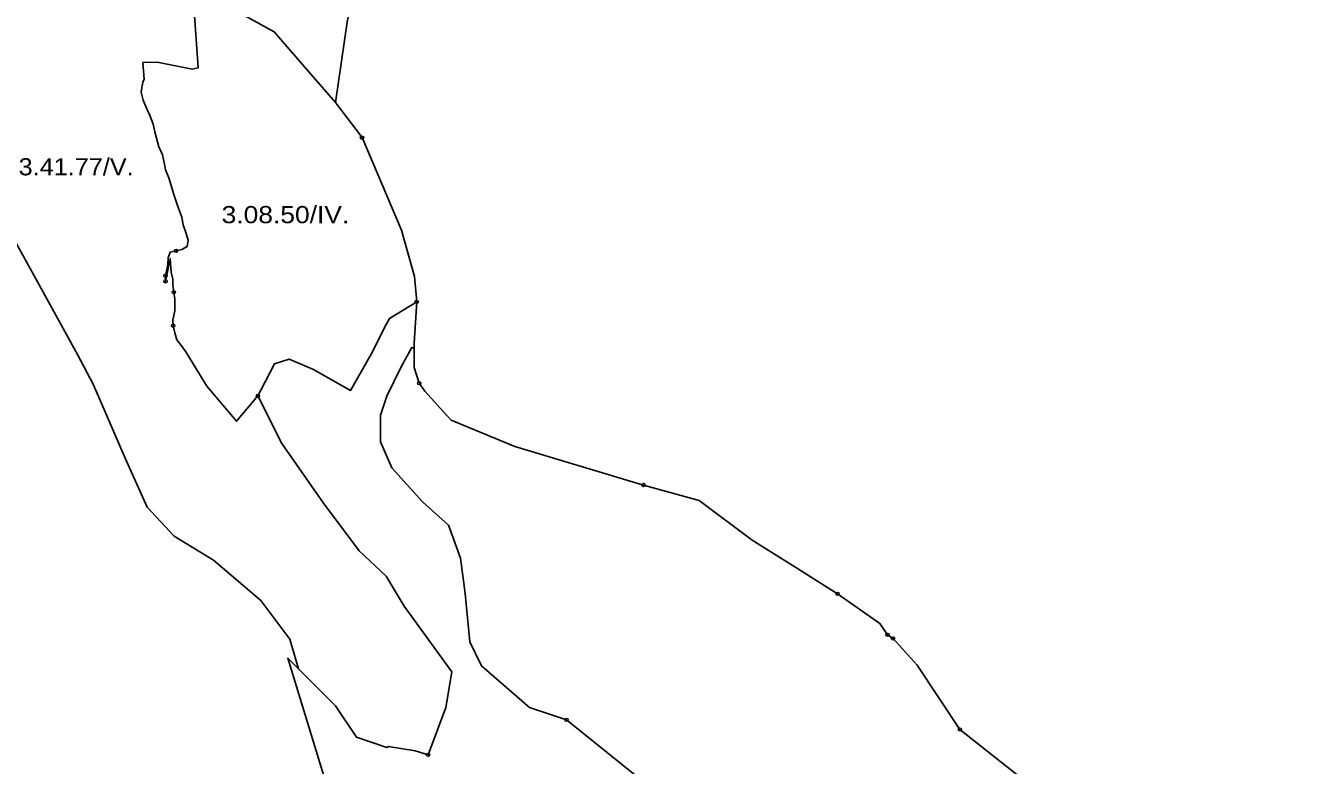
# Model space of a CAD drawing. Extents: x -650455 to -642254, y -1075222 to -1066610.
# Drawn here: x -645923 to -645184, y -1070477 to -1070045 of the extents above; entities that cross this region are included whole.
import ezdxf
from ezdxf.enums import TextEntityAlignment as Align

# ---------------------------------------------------------------- set-up
doc = ezdxf.new("R2010")
doc.units = 0
doc.header["$LTSCALE"] = 4
doc.header["$PDMODE"] = 32
doc.header["$PDSIZE"] = 2
for name, color, linetype, lineweight in [('1', 7, 'Continuous', 25), ('11', 7, 'Continuous', 13), ('12', 7, 'Continuous', 13), ('14', 7, 'Continuous', 13), ('15', 7, 'Continuous', 13)]:
    doc.layers.add(name, color=color, linetype=linetype, lineweight=lineweight)
doc.layers.add('2', color=7, linetype='Continuous')

msp = doc.modelspace()

# ---------------------------------------------------------------- linework, layer by layer
at = {"layer": '1'}
for points in [[(-645827.805, -1070170.331), (-645829.232, -1070165.834), (-645830.719, -1070161.367), (-645831.596, -1070156.856), (-645833.216, -1070152.24), (-645834.881, -1070147.654), (-645836.323, -1070143.068), (-645837.765, -1070138.483), (-645839.206, -1070133.897), (-645841.079, -1070129.341), (-645841.912, -1070124.948), (-645842.729, -1070120.556), (-645844.914, -1070115.94), (-645847.337, -1070107.036), (-645848.229, -1070102.643), (-645850.013, -1070097.968), (-645852.064, -1070093.293), (-645854.131, -1070088.618), (-645855.32, -1070084.018), (-645854.309, -1070077.93), (-645853.462, -1070076.604), (-645854.242, -1070066.719), (-645845.918, -1070066.459), (-645825.452, -1070070.498), (-645821.972, -1070069.724), (-645825.17, -1070025.403)], [(-645825.17, -1070025.403), (-645821.972, -1070069.724), (-645825.452, -1070070.498), (-645845.918, -1070066.459), (-645854.242, -1070066.719), (-645853.462, -1070076.604), (-645854.309, -1070077.93), (-645855.32, -1070084.018), (-645854.131, -1070088.618), (-645852.064, -1070093.293), (-645850.013, -1070097.968), (-645848.229, -1070102.643), (-645847.337, -1070107.036), (-645844.914, -1070115.94), (-645842.729, -1070120.556)], [(-645817.043, -1070027.048), (-645777.762, -1070048.899), (-645757.472, -1070072.051), (-645741.915, -1070090.098)], [(-645735.031, -1070041.903), (-645741.915, -1070090.098), (-645757.472, -1070072.051), (-645777.762, -1070048.899), (-645817.043, -1070027.048)], [(-645474.208, -1070360.748), (-645499.088, -1070345.198), (-645530.032, -1070322.029), (-645562.376, -1070313.01), (-645637.482, -1070290.618), (-645674.491, -1070275.223), (-645677.134, -1070272.424), (-645689.807, -1070258.381), (-645693.219, -1070253.691), (-645696.21, -1070244.446), (-645696.21, -1070233.478), (-645696.21, -1070230.279), (-645694.628, -1070206.315), (-645696, -1070191.501), (-645703.5, -1070164.501), (-645726.5, -1070110.501), (-645741.915, -1070090.098), (-645735.031, -1070041.903)], [(-645741.915, -1070090.098), (-645726.5, -1070110.501), (-645703.5, -1070164.501), (-645696, -1070191.501), (-645694.628, -1070206.315), (-645710.517, -1070216.036), (-645712.468, -1070219.418), (-645721.12, -1070236.652), (-645733.239, -1070257.86), (-645750.708, -1070248.033), (-645754.87, -1070245.692), (-645768.918, -1070239.709), (-645777.502, -1070242.31), (-645785.567, -1070257.658), (-645787.196, -1070260.996), (-645799.614, -1070275.867), (-645817.043, -1070255.317), (-645829.113, -1070235.357), (-645831.774, -1070231.886), (-645834.45, -1070228.415), (-645835.52, -1070224.275), (-645836.59, -1070220.135), (-645836.754, -1070216.783), (-645836.218, -1070214.145), (-645835.683, -1070211.506), (-645835.698, -1070204.743), (-645836.248, -1070200.618), (-645836.798, -1070196.493), (-645836.694, -1070192.948), (-645837.839, -1070188.926), (-645838.285, -1070181.137), (-645841.065, -1070194.285), (-645841.065, -1070190.985), (-645839.771, -1070184.475), (-645839.593, -1070180.632), (-645838.3, -1070177.339), (-645834.881, -1070176.492), (-645831.462, -1070175.645), (-645828.37, -1070173.935), (-645827.805, -1070170.331)], [(-645842.729, -1070120.556), (-645841.912, -1070124.948), (-645841.079, -1070129.341), (-645839.206, -1070133.897), (-645837.765, -1070138.483), (-645836.323, -1070143.068), (-645834.881, -1070147.654), (-645833.216, -1070152.24), (-645831.596, -1070156.856), (-645830.719, -1070161.367), (-645829.232, -1070165.834), (-645827.805, -1070170.331), (-645828.37, -1070173.935), (-645831.462, -1070175.645), (-645834.881, -1070176.492), (-645838.3, -1070177.339), (-645839.593, -1070180.632), (-645839.771, -1070184.475), (-645841.065, -1070190.985), (-645841.065, -1070194.285), (-645838.285, -1070181.137), (-645837.839, -1070188.926), (-645836.694, -1070192.948), (-645836.798, -1070196.493), (-645836.248, -1070200.618), (-645835.698, -1070204.743), (-645835.683, -1070211.506), (-645836.218, -1070214.145), (-645836.754, -1070216.783), (-645836.59, -1070220.135), (-645835.52, -1070224.275), (-645834.45, -1070228.415), (-645831.774, -1070231.886), (-645829.113, -1070235.357), (-645817.043, -1070255.317), (-645799.614, -1070275.867), (-645787.196, -1070260.996), (-645773.285, -1070288.817), (-645748.941, -1070323.593), (-645728.075, -1070351.415)], [(-645937.054, -1070142.706), (-645934.808, -1070159.546), (-645892.146, -1070237.292), (-645883.165, -1070254.133), (-645864.64, -1070297.356), (-645851.729, -1070325.985), (-645836.012, -1070342.825), (-645812.997, -1070356.859), (-645785.491, -1070380.435), (-645768.65, -1070402.889), (-645763.626, -1070420.193)], [(-645728.075, -1070351.415), (-645712.426, -1070366.195), (-645701.993, -1070383.583), (-645674.172, -1070421.837), (-645677.649, -1070442.703), (-645688.022, -1070470.362), (-645695.5, -1070468.001), (-645711, -1070465.5), (-645712.054, -1070466.012), (-645729.814, -1070460.091), (-645741.986, -1070441.834), (-645763.626, -1070420.193), (-645768.65, -1070402.889), (-645785.491, -1070380.435), (-645812.997, -1070356.859), (-645836.012, -1070342.825), (-645851.729, -1070325.985), (-645864.64, -1070297.356), (-645883.165, -1070254.133), (-645892.146, -1070237.292), (-645934.808, -1070159.546)], [(-645749.009, -1070481.878), (-645769.807, -1070414.012), (-645763.626, -1070420.193), (-645741.986, -1070441.834), (-645729.814, -1070460.091), (-645712.054, -1070466.012), (-645711, -1070465.5), (-645695.5, -1070468.001), (-645688.022, -1070470.362), (-645677.649, -1070442.703), (-645674.172, -1070421.837), (-645701.993, -1070383.583), (-645712.426, -1070366.195), (-645728.075, -1070351.415), (-645748.941, -1070323.593), (-645773.285, -1070288.817), (-645787.196, -1070260.996), (-645785.567, -1070257.658), (-645777.502, -1070242.31), (-645768.918, -1070239.709), (-645754.87, -1070245.692), (-645750.708, -1070248.033), (-645733.239, -1070257.86), (-645721.12, -1070236.652), (-645712.468, -1070219.418), (-645710.517, -1070216.036), (-645694.628, -1070206.315), (-645696.21, -1070230.279), (-645696.21, -1070233.478)], [(-645696.21, -1070233.478), (-645697.505, -1070232.772), (-645703.725, -1070244.123), (-645712.121, -1070261.228), (-645715.698, -1070272.269), (-645715.698, -1070287.819), (-645709.167, -1070303.058), (-645691.285, -1070322.806), (-645676.046, -1070336.49), (-645669.048, -1070355.616), (-645666.347, -1070376.193), (-645663.739, -1070404.449), (-645656.783, -1070418.36), (-645628.962, -1070442.703), (-645607.333, -1070449.913), (-645567.5, -1070482)], [(-645656.783, -1070418.36), (-645663.739, -1070404.449), (-645666.347, -1070376.193), (-645669.048, -1070355.616), (-645676.046, -1070336.49), (-645691.285, -1070322.806), (-645709.167, -1070303.058), (-645715.698, -1070287.819), (-645715.698, -1070272.269), (-645712.121, -1070261.228), (-645703.725, -1070244.123), (-645697.505, -1070232.772), (-645696.21, -1070233.478)], [(-645696.21, -1070233.478), (-645696.21, -1070244.446), (-645693.219, -1070253.691), (-645689.807, -1070258.381), (-645677.134, -1070272.424), (-645674.491, -1070275.223), (-645637.482, -1070290.618), (-645562.376, -1070313.01), (-645530.032, -1070322.029), (-645499.088, -1070345.198), (-645474.208, -1070360.748), (-645449.328, -1070376.453), (-645424.604, -1070393.714), (-645420.219, -1070400.367), (-645417, -1070402.501), (-645403, -1070418.001), (-645378, -1070455.501), (-645302, -1070515.501), (-645282.5, -1070523), (-645245, -1070532.501), (-645235, -1070537.001), (-645188.5, -1070544.501), (-645179.5, -1070566.5)], [(-644777, -1070514), (-644832, -1070537.001), (-644888.5, -1070557.001), (-644982, -1070577.501), (-645008.5, -1070579.5), (-645087, -1070571), (-645188.5, -1070544.501), (-645235, -1070537.001), (-645245, -1070532.501), (-645282.5, -1070523), (-645302, -1070515.501), (-645378, -1070455.501), (-645403, -1070418.001), (-645417, -1070402.501), (-645420.219, -1070400.367), (-645424.604, -1070393.714), (-645449.328, -1070376.453), (-645474.208, -1070360.748)], [(-645763.626, -1070420.193), (-645769.807, -1070414.012), (-645749.009, -1070481.878), (-645729, -1070511.501), (-645671, -1070582), (-645617, -1070664.5), (-645571.435, -1070712.939), (-645562, -1070787.001), (-645566, -1070859), (-645576.5, -1070881.501), (-645600.5, -1070904.001), (-645607.5, -1070909.001), (-645646.5, -1070921.501), (-645665, -1070920), (-645678.5, -1070914.5), (-645700.5, -1070899.5), (-645723, -1070872.001), (-645779.5, -1070752.5), (-645785.632, -1070741.019), (-645799.865, -1070741.1), (-645840.313, -1070737.642), (-645880.438, -1070727.108), (-645920.242, -1070713.679), (-645927.962, -1070711.588)], [(-645179.5, -1070600), (-645195.5, -1070648), (-645202, -1070658.501), (-645200.205, -1070663.392), (-645234.5, -1070674.001), (-645317, -1070688), (-645345.5, -1070688.5), (-645375, -1070683.001), (-645431.5, -1070664), (-645472, -1070640.5), (-645491.5, -1070620.501), (-645509.5, -1070585.001), (-645555.128, -1070497.341), (-645567.5, -1070482), (-645607.333, -1070449.913), (-645628.962, -1070442.703), (-645656.783, -1070418.36)]]:
    msp.add_lwpolyline(points, dxfattribs=at)
at = {"layer": '11'}
for points in [[(-645725.467, -1069844.112), (-645715.034, -1069885.843), (-645715.034, -1069948.441), (-645711.556, -1069990.173), (-645714.013, -1070000), (-645715.034, -1070004.084), (-645728.075, -1070017.56), (-645735.031, -1070041.903), (-645741.915, -1070090.098), (-645726.5, -1070110.501), (-645703.5, -1070164.501), (-645696, -1070191.501), (-645694.628, -1070206.315), (-645696.21, -1070230.279), (-645696.21, -1070233.478), (-645696.21, -1070244.446), (-645693.219, -1070253.691)], [(-645693.219, -1070253.691), (-645689.807, -1070258.381), (-645677.134, -1070272.424), (-645674.491, -1070275.223), (-645637.482, -1070290.618), (-645562.376, -1070313.01), (-645530.032, -1070322.029), (-645499.088, -1070345.198)], [(-645499.088, -1070345.198), (-645474.208, -1070360.748), (-645449.328, -1070376.453)], [(-645449.328, -1070376.453), (-645424.604, -1070393.714), (-645420.219, -1070400.367), (-645417, -1070402.501)], [(-645417, -1070402.501), (-645403, -1070418.001), (-645378, -1070455.501)], [(-645378, -1070455.501), (-645302, -1070515.501), (-645282.5, -1070523), (-645245, -1070532.501), (-645235, -1070537.001), (-645188.5, -1070544.501), (-645087, -1070571)]]:
    msp.add_lwpolyline(points, dxfattribs=at)
for p in [(-645693.219, -1070253.691), (-645449.328, -1070376.453), (-645417, -1070402.501), (-645378, -1070455.501)]:
    msp.add_point(p, dxfattribs=at)
at = {"layer": '12'}
for points in [[(-645850.5, -1069989.001), (-645845.117, -1070000), (-645839, -1070012.5), (-645829.689, -1070021.439), (-645826.5, -1070024.5), (-645825.17, -1070025.403), (-645817.043, -1070027.048), (-645777.762, -1070048.899), (-645757.472, -1070072.051), (-645741.915, -1070090.098), (-645735.031, -1070041.903), (-645728.075, -1070017.56), (-645715.034, -1070004.084)], [(-645660.21, -1070679.591), (-645655.86, -1070681.476), (-645654.054, -1070682.261), (-645655.409, -1070687.006), (-645656.426, -1070693.784), (-645656.765, -1070697.173), (-645654.518, -1070702.587), (-645612.056, -1070669.756), (-645617, -1070664.5), (-645671, -1070582), (-645729, -1070511.501), (-645749.009, -1070481.878), (-645769.807, -1070414.012), (-645763.626, -1070420.193), (-645768.65, -1070402.889), (-645785.491, -1070380.435), (-645812.997, -1070356.859), (-645836.012, -1070342.825), (-645851.729, -1070325.985), (-645864.64, -1070297.356), (-645883.165, -1070254.133), (-645892.146, -1070237.292), (-645934.808, -1070159.546)], [(-645562.376, -1070313.01), (-645637.482, -1070290.618), (-645674.491, -1070275.223), (-645677.134, -1070272.424), (-645689.807, -1070258.381), (-645693.219, -1070253.691), (-645696.21, -1070244.446), (-645696.21, -1070233.478), (-645697.505, -1070232.772), (-645703.725, -1070244.123), (-645712.121, -1070261.228), (-645715.698, -1070272.269), (-645715.698, -1070287.819), (-645709.167, -1070303.058), (-645691.285, -1070322.806), (-645676.046, -1070336.49), (-645669.048, -1070355.616), (-645666.347, -1070376.193), (-645663.739, -1070404.449), (-645656.783, -1070418.36), (-645628.962, -1070442.703), (-645607.333, -1070449.913)], [(-645420.219, -1070400.367), (-645424.604, -1070393.714), (-645449.328, -1070376.453), (-645474.208, -1070360.748), (-645499.088, -1070345.198), (-645530.032, -1070322.029), (-645562.376, -1070313.01)], [(-645195.5, -1070648), (-645179.5, -1070600), (-645179.5, -1070566.5), (-645188.5, -1070544.501), (-645235, -1070537.001), (-645245, -1070532.501), (-645282.5, -1070523), (-645302, -1070515.501), (-645378, -1070455.501), (-645403, -1070418.001), (-645417, -1070402.501), (-645420.219, -1070400.367)], [(-645607.333, -1070449.913), (-645567.5, -1070482), (-645555.128, -1070497.341), (-645509.5, -1070585.001), (-645491.5, -1070620.501), (-645472, -1070640.5), (-645431.5, -1070664)]]:
    msp.add_lwpolyline(points, dxfattribs=at)
for p in [(-645562.376, -1070313.01), (-645420.219, -1070400.367), (-645607.333, -1070449.913)]:
    msp.add_point(p, dxfattribs=at)
at = {"layer": '14'}
for points in [[(-645825.17, -1070025.403), (-645821.972, -1070069.724), (-645825.452, -1070070.498), (-645845.918, -1070066.459), (-645854.242, -1070066.719), (-645853.462, -1070076.604), (-645854.309, -1070077.93), (-645855.32, -1070084.018), (-645854.131, -1070088.618), (-645852.064, -1070093.293), (-645850.013, -1070097.968), (-645848.229, -1070102.643), (-645847.337, -1070107.036), (-645844.914, -1070115.94), (-645842.729, -1070120.556), (-645841.912, -1070124.948), (-645841.079, -1070129.341), (-645839.206, -1070133.897), (-645837.765, -1070138.483), (-645836.323, -1070143.068), (-645834.881, -1070147.654), (-645833.216, -1070152.24), (-645831.596, -1070156.856), (-645830.719, -1070161.367), (-645829.232, -1070165.834), (-645827.805, -1070170.331), (-645828.37, -1070173.935), (-645831.462, -1070175.645), (-645834.881, -1070176.492), (-645838.3, -1070177.339), (-645839.593, -1070180.632), (-645839.771, -1070184.475), (-645841.065, -1070190.985), (-645841.065, -1070194.285)], [(-645726.5, -1070110.501), (-645741.915, -1070090.098), (-645757.472, -1070072.051), (-645777.762, -1070048.899), (-645817.043, -1070027.048)], [(-645694.628, -1070206.315), (-645696, -1070191.501), (-645703.5, -1070164.501), (-645726.5, -1070110.501)], [(-645841.065, -1070194.285), (-645838.285, -1070181.137), (-645837.839, -1070188.926), (-645836.694, -1070192.948), (-645836.798, -1070196.493), (-645836.248, -1070200.618), (-645835.698, -1070204.743), (-645835.683, -1070211.506), (-645836.218, -1070214.145), (-645836.754, -1070216.783), (-645836.59, -1070220.135)], [(-645836.59, -1070220.135), (-645835.52, -1070224.275), (-645834.45, -1070228.415), (-645831.774, -1070231.886), (-645829.113, -1070235.357), (-645817.043, -1070255.317), (-645799.614, -1070275.867), (-645787.196, -1070260.996), (-645785.567, -1070257.658), (-645777.502, -1070242.31), (-645768.918, -1070239.709), (-645754.87, -1070245.692), (-645750.708, -1070248.033), (-645733.239, -1070257.86), (-645721.12, -1070236.652), (-645712.468, -1070219.418), (-645710.517, -1070216.036), (-645694.628, -1070206.315)], [(-645567.5, -1070482), (-645607.333, -1070449.913), (-645628.962, -1070442.703), (-645656.783, -1070418.36), (-645663.739, -1070404.449), (-645666.347, -1070376.193), (-645669.048, -1070355.616), (-645676.046, -1070336.49), (-645691.285, -1070322.806), (-645709.167, -1070303.058), (-645715.698, -1070287.819), (-645715.698, -1070272.269), (-645712.121, -1070261.228), (-645703.725, -1070244.123), (-645697.505, -1070232.772), (-645696.21, -1070233.478), (-645696.21, -1070230.279), (-645694.628, -1070206.315), (-645710.517, -1070216.036), (-645712.468, -1070219.418), (-645721.12, -1070236.652), (-645733.239, -1070257.86), (-645750.708, -1070248.033), (-645754.87, -1070245.692), (-645768.918, -1070239.709), (-645777.502, -1070242.31), (-645785.567, -1070257.658), (-645787.196, -1070260.996)], [(-645787.196, -1070260.996), (-645773.285, -1070288.817), (-645748.941, -1070323.593), (-645728.075, -1070351.415), (-645712.426, -1070366.195), (-645701.993, -1070383.583), (-645674.172, -1070421.837), (-645677.649, -1070442.703), (-645688.022, -1070470.362), (-645695.5, -1070468.001), (-645711, -1070465.5), (-645712.054, -1070466.012), (-645729.814, -1070460.091), (-645741.986, -1070441.834), (-645763.626, -1070420.193), (-645769.807, -1070414.012), (-645749.009, -1070481.878), (-645729, -1070511.501), (-645671, -1070582), (-645617, -1070664.5), (-645616.574, -1070664.953), (-645612.056, -1070669.756), (-645571.435, -1070712.939)]]:
    msp.add_lwpolyline(points, dxfattribs=at)
for p in [(-645726.5, -1070110.501), (-645841.065, -1070194.285), (-645694.628, -1070206.315), (-645836.59, -1070220.135), (-645787.196, -1070260.996)]:
    msp.add_point(p, dxfattribs=at)
at = {"layer": '15'}
for points in [[(-645834.881, -1070176.492), (-645831.462, -1070175.645), (-645828.37, -1070173.935), (-645827.805, -1070170.331), (-645829.232, -1070165.834), (-645830.719, -1070161.367), (-645831.596, -1070156.856), (-645833.216, -1070152.24), (-645834.881, -1070147.654), (-645836.323, -1070143.068), (-645837.765, -1070138.483), (-645839.206, -1070133.897), (-645841.079, -1070129.341), (-645841.912, -1070124.948), (-645842.729, -1070120.556), (-645844.914, -1070115.94), (-645847.337, -1070107.036), (-645848.229, -1070102.643), (-645850.013, -1070097.968), (-645852.064, -1070093.293), (-645854.131, -1070088.618), (-645855.32, -1070084.018), (-645854.309, -1070077.93), (-645853.462, -1070076.604), (-645854.242, -1070066.719), (-645845.918, -1070066.459), (-645825.452, -1070070.498), (-645821.972, -1070069.724), (-645825.17, -1070025.403)], [(-645949.403, -1070096.114), (-645949.965, -1070116.884), (-645937.054, -1070142.706), (-645934.808, -1070159.546), (-645892.146, -1070237.292), (-645883.165, -1070254.133), (-645864.64, -1070297.356), (-645851.729, -1070325.985), (-645836.012, -1070342.825), (-645812.997, -1070356.859), (-645785.491, -1070380.435), (-645768.65, -1070402.889), (-645763.626, -1070420.193), (-645741.986, -1070441.834), (-645729.814, -1070460.091), (-645712.054, -1070466.012), (-645711, -1070465.5), (-645695.5, -1070468.001), (-645688.022, -1070470.362)], [(-645841.065, -1070190.985), (-645839.771, -1070184.475), (-645839.593, -1070180.632), (-645838.3, -1070177.339), (-645834.881, -1070176.492)], [(-645836.248, -1070200.618), (-645836.798, -1070196.493), (-645836.694, -1070192.948), (-645837.839, -1070188.926), (-645838.285, -1070181.137), (-645841.065, -1070194.285), (-645841.065, -1070190.985)], [(-645688.022, -1070470.362), (-645677.649, -1070442.703), (-645674.172, -1070421.837), (-645701.993, -1070383.583), (-645712.426, -1070366.195), (-645728.075, -1070351.415), (-645748.941, -1070323.593), (-645773.285, -1070288.817), (-645787.196, -1070260.996), (-645799.614, -1070275.867), (-645817.043, -1070255.317), (-645829.113, -1070235.357), (-645831.774, -1070231.886), (-645834.45, -1070228.415), (-645835.52, -1070224.275), (-645836.59, -1070220.135), (-645836.754, -1070216.783), (-645836.218, -1070214.145), (-645835.683, -1070211.506), (-645835.698, -1070204.743), (-645836.248, -1070200.618)]]:
    msp.add_lwpolyline(points, dxfattribs=at)
for p in [(-645834.881, -1070176.492), (-645841.065, -1070190.985), (-645836.248, -1070200.618), (-645688.022, -1070470.362)]:
    msp.add_point(p, dxfattribs=at)

# ---------------------------------------------------------------- texts
at = {"layer": '2'}
for s, width, p in [('3.41.77/V.', 1.1, (-645893.136, -1070132.488)), ('3.08.50/IV.', 1.15, (-645771.14, -1070160.379))]:
    msp.add_text(s, height=10, dxfattribs=dict(at, width=width)).set_placement(p, align=Align.CENTER)

doc.saveas('drawing.dxf')
